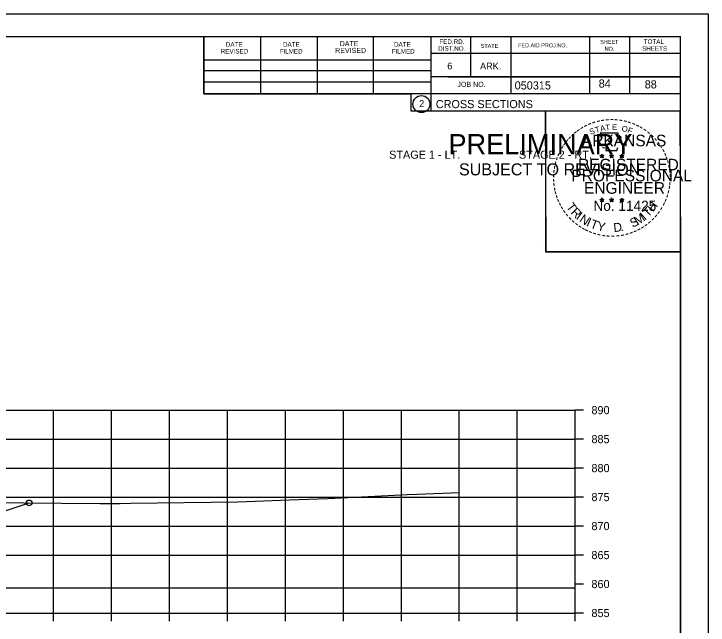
# Model space of a CAD drawing. Extents: x 1486524 to 1499135, y 326561 to 337924.
# Drawn here: x 1489026 to 1489145.8, y 335447.3 to 335552.7 of the extents above; entities that cross this region are included whole.
import ezdxf

# ---------------------------------------------------------------- set-up
doc = ezdxf.new("R2010")
doc.units = 0
for name, color, linetype in [('Default', 7, 'Continuous'), ('E_Const Align', 7, 'Continuous'), ('E_Const Align Station', 7, 'Continuous'), ('E_Ownership Information', 7, 'Continuous'), ('E_Property Line', 7, 'Continuous'), ('E_Quarter Calls', 7, 'Continuous'), ('E_Section Line', 7, 'Continuous'), ('E_Station Offset', 7, 'Continuous'), ('E_Title Sheet', 7, 'Continuous'), ('E_Tract Number', 7, 'Continuous'), ('S_SIXTEEN_SECTION', 7, 'Continuous')]:
    doc.layers.add(name, color=color, linetype=linetype)

msp = doc.modelspace()

# ---------------------------------------------------------------- linework, layer by layer
at = {"layer": 'E_Const Align'}
for p, q in [((1489122.89, 335449.34), (1489122.89, 335484.34)), ((1489124.29, 335484.34), (1489122.89, 335484.34)), ((1489124.29, 335479.34), (1489122.89, 335479.34)), ((1489124.29, 335474.34), (1489122.89, 335474.34)), ((1489124.29, 335469.34), (1489122.89, 335469.34)), ((1489124.29, 335464.34), (1489122.89, 335464.34)), ((1489124.29, 335459.34), (1489122.89, 335459.34)), ((1489124.29, 335454.34), (1489122.89, 335454.34)), ((1488842.89, 335449.34), (1489122.89, 335449.34)), ((1489032.89, 335447.94), (1489032.89, 335449.34)), ((1489042.89, 335447.94), (1489042.89, 335449.34)), ((1489052.89, 335447.94), (1489052.89, 335449.34)), ((1489062.89, 335447.94), (1489062.89, 335449.34)), ((1489072.89, 335447.94), (1489072.89, 335449.34)), ((1489082.89, 335447.94), (1489082.89, 335449.34)), ((1489092.89, 335447.94), (1489092.89, 335449.34)), ((1489102.89, 335447.94), (1489102.89, 335449.34)), ((1489112.89, 335447.94), (1489112.89, 335449.34)), ((1489122.89, 335447.94), (1489122.89, 335449.34)), ((1489124.29, 335449.34), (1489122.89, 335449.34))]:
    msp.add_line(p, q, dxfattribs=at)
at = {"layer": 'E_Ownership Information'}
for p, q in [((1488842.89, 335484.34), (1489122.89, 335484.34)), ((1489032.89, 335449.34), (1489032.89, 335484.34)), ((1489042.89, 335449.34), (1489042.89, 335484.34)), ((1489052.89, 335449.34), (1489052.89, 335484.34)), ((1489062.89, 335449.34), (1489062.89, 335484.34)), ((1489072.89, 335449.34), (1489072.89, 335484.34)), ((1489082.89, 335449.34), (1489082.89, 335484.34)), ((1489092.89, 335449.34), (1489092.89, 335484.34)), ((1489102.89, 335449.34), (1489102.89, 335484.34)), ((1489112.89, 335449.34), (1489112.89, 335484.34)), ((1489122.89, 335449.34), (1489122.89, 335484.34)), ((1488842.89, 335479.34), (1489122.89, 335479.34)), ((1488842.89, 335474.34), (1489122.89, 335474.34)), ((1488842.89, 335469.34), (1489122.89, 335469.34)), ((1488842.89, 335464.34), (1489122.89, 335464.34)), ((1488842.89, 335459.34), (1489122.89, 335459.34)), ((1488842.69, 335453.71), (1489122.69, 335453.71)), ((1488842.89, 335449.34), (1489122.89, 335449.34))]:
    msp.add_line(p, q, dxfattribs=at)
at = {"layer": 'E_Property Line'}
for p, q in [((1488824.89, 335548.8), (1489141.07, 335548.8)), ((1489058.81, 335538.92), (1489058.81, 335548.8)), ((1489097.97, 335548.8), (1489097.97, 335536)), ((1489104.81, 335548.8), (1489104.81, 335541.86)), ((1489111.75, 335548.8), (1489111.75, 335538.92)), ((1489125.33, 335548.8), (1489125.33, 335538.92)), ((1489132.27, 335548.8), (1489132.27, 335538.92)), ((1489141.07, 335343.34), (1489141.07, 335548.8)), ((1489068.67, 335538.92), (1489068.67, 335548.6)), ((1489078.43, 335538.92), (1489078.43, 335548.6)), ((1489088.11, 335538.92), (1489088.11, 335548.6)), ((1489141.07, 335545.86), (1489097.97, 335545.86)), ((1489141.07, 335545.88), (1489141.07, 335545.88)), ((1489058.81, 335544.78), (1489097.97, 335544.78)), ((1489058.81, 335542.92), (1489097.97, 335542.92)), ((1489141.07, 335541.86), (1489097.97, 335541.86)), ((1489100.93, 335541.86), (1489141.07, 335541.86)), ((1489058.81, 335538.92), (1489058.81, 335540.98)), ((1489058.81, 335540.98), (1489097.97, 335540.98)), ((1489141.07, 335538.92), (1489058.81, 335538.92)), ((1489097.97, 335536), (1489141.07, 335536))]:
    msp.add_line(p, q, dxfattribs=at)
msp.add_circle((1489096.35, 335537.14), 1.47, dxfattribs=at)
at = {"layer": 'E_Quarter Calls'}
for p, q in [((1488812.48, 335552.7), (1489145.82, 335552.7)), ((1489117.1, 335513.55), (1489117.1, 335513.55))]:
    msp.add_line(p, q, dxfattribs=at)
for points in [[(1488812.48, 335552.7), (1489145.82, 335552.7), (1489145.82, 335339.36), (1488812.48, 335339.36)], [(1489058.81, 335548.8), (1489058.81, 335538.92), (1489094.54, 335538.92), (1489094.54, 335536), (1489117.74, 335536), (1489117.74, 335511.67), (1489141.07, 335511.67), (1489141.07, 335343.34), (1488824.89, 335343.34), (1488824.89, 335548.8)], [(1489117.74, 335536), (1489140.94, 335536), (1489141.07, 335511.67), (1489117.86, 335511.67)]]:
    msp.add_lwpolyline(points, close=True, dxfattribs=at)
msp.add_circle((1489028.67, 335468.33), 0.5, dxfattribs=at)
at = {"layer": 'E_Title Sheet'}
msp.add_lwpolyline([(1488930.55, 335466.05), (1488940.89, 335462.61), (1488946.74, 335464.07), (1488952.89, 335465.61), (1488958.89, 335465.85), (1488982.89, 335466.47), (1488994.89, 335466.78), (1489002.89, 335466.99), (1489008.22, 335465.65), (1489012.89, 335464.49), (1489015.01, 335463.78), (1489028.67, 335468.33)], dxfattribs=at)
at = {"layer": 'E_Tract Number'}
msp.add_lwpolyline([(1489021.13, 335468.38), (1489040.88, 335468.26), (1489043.85, 335468.24), (1489044.38, 335468.24), (1489046.19, 335468.27), (1489064.69, 335468.53), (1489073.53, 335468.87), (1489080.23, 335469.08), (1489087.19, 335469.45), (1489093.9, 335469.76), (1489095.55, 335469.85), (1489102.91, 335470.14)], dxfattribs=at)
at = {"layer": 'S_SIXTEEN_SECTION'}
for p, q in [((1489127.5, 335528.51), (1489127.46, 335528.26)), ((1489127.5, 335528.15), (1489127.5, 335528.51)), ((1489127.5, 335528.51), (1489127.55, 335528.26)), ((1489129.17, 335528.51), (1489129.13, 335528.26)), ((1489129.17, 335528.15), (1489129.17, 335528.51)), ((1489129.17, 335528.51), (1489129.22, 335528.26)), ((1489130.93, 335528.5), (1489130.89, 335528.25)), ((1489130.93, 335528.14), (1489130.93, 335528.5)), ((1489130.93, 335528.5), (1489130.98, 335528.25)), ((1489127.15, 335528.26), (1489127.5, 335528.15)), ((1489127.15, 335528.26), (1489127.4, 335528.22)), ((1489127.15, 335528.26), (1489127.39, 335528.14)), ((1489127.28, 335527.85), (1489127.5, 335528.15)), ((1489127.28, 335527.85), (1489127.41, 335528.1)), ((1489127.28, 335527.85), (1489127.5, 335528.07)), ((1489127.85, 335528.26), (1489127.5, 335528.15)), ((1489127.71, 335527.85), (1489127.5, 335528.15)), ((1489127.71, 335527.85), (1489127.5, 335528.07)), ((1489127.85, 335528.26), (1489127.56, 335528.21)), ((1489127.71, 335527.85), (1489127.58, 335528.14)), ((1489127.85, 335528.26), (1489127.64, 335528.16)), ((1489128.82, 335528.26), (1489129.17, 335528.15)), ((1489128.82, 335528.26), (1489129.07, 335528.22)), ((1489128.82, 335528.26), (1489129.06, 335528.14)), ((1489128.95, 335527.85), (1489129.17, 335528.15)), ((1489128.95, 335527.85), (1489129.08, 335528.1)), ((1489128.95, 335527.85), (1489129.17, 335528.07)), ((1489129.52, 335528.26), (1489129.17, 335528.15)), ((1489129.38, 335527.85), (1489129.17, 335528.15)), ((1489129.38, 335527.85), (1489129.17, 335528.07)), ((1489129.52, 335528.26), (1489129.23, 335528.21)), ((1489129.38, 335527.85), (1489129.25, 335528.14)), ((1489129.52, 335528.26), (1489129.31, 335528.16)), ((1489130.58, 335528.25), (1489130.93, 335528.14)), ((1489130.58, 335528.25), (1489130.84, 335528.2)), ((1489130.58, 335528.25), (1489130.82, 335528.13)), ((1489130.72, 335527.84), (1489130.93, 335528.14)), ((1489130.72, 335527.84), (1489130.84, 335528.08)), ((1489130.72, 335527.84), (1489130.93, 335528.06)), ((1489131.28, 335528.25), (1489130.93, 335528.14)), ((1489131.15, 335527.84), (1489130.93, 335528.14)), ((1489131.15, 335527.84), (1489130.93, 335528.05)), ((1489131.28, 335528.25), (1489130.99, 335528.2)), ((1489131.15, 335527.84), (1489131.01, 335528.13)), ((1489131.28, 335528.25), (1489131.08, 335528.15)), ((1489127.15, 335520.69), (1489127.5, 335520.58)), ((1489127.15, 335520.69), (1489127.4, 335520.64)), ((1489127.15, 335520.69), (1489127.38, 335520.57)), ((1489127.28, 335520.28), (1489127.5, 335520.58)), ((1489127.28, 335520.28), (1489127.41, 335520.52)), ((1489127.28, 335520.28), (1489127.49, 335520.5)), ((1489127.5, 335520.94), (1489127.45, 335520.69)), ((1489127.71, 335520.28), (1489127.49, 335520.49)), ((1489127.5, 335520.58), (1489127.5, 335520.94)), ((1489127.5, 335520.94), (1489127.54, 335520.69)), ((1489127.84, 335520.69), (1489127.5, 335520.58)), ((1489127.71, 335520.28), (1489127.5, 335520.58)), ((1489127.84, 335520.69), (1489127.56, 335520.64)), ((1489127.71, 335520.28), (1489127.57, 335520.57)), ((1489127.84, 335520.69), (1489127.64, 335520.59)), ((1489128.82, 335520.69), (1489129.16, 335520.58)), ((1489128.82, 335520.69), (1489129.07, 335520.64)), ((1489128.82, 335520.69), (1489129.05, 335520.57)), ((1489128.95, 335520.28), (1489129.16, 335520.58)), ((1489128.95, 335520.28), (1489129.07, 335520.52)), ((1489128.95, 335520.28), (1489129.16, 335520.5)), ((1489129.16, 335520.94), (1489129.12, 335520.69)), ((1489129.16, 335520.58), (1489129.16, 335520.94)), ((1489129.16, 335520.94), (1489129.21, 335520.69)), ((1489129.51, 335520.69), (1489129.16, 335520.58)), ((1489129.38, 335520.28), (1489129.16, 335520.58)), ((1489129.38, 335520.28), (1489129.16, 335520.49)), ((1489129.51, 335520.69), (1489129.23, 335520.64)), ((1489129.38, 335520.28), (1489129.24, 335520.57)), ((1489129.51, 335520.69), (1489129.31, 335520.59)), ((1489130.58, 335520.68), (1489130.93, 335520.57)), ((1489130.58, 335520.68), (1489130.84, 335520.63)), ((1489130.58, 335520.68), (1489130.82, 335520.56)), ((1489130.72, 335520.27), (1489130.93, 335520.57)), ((1489130.72, 335520.27), (1489130.84, 335520.51)), ((1489130.72, 335520.27), (1489130.93, 335520.49)), ((1489130.93, 335520.93), (1489130.89, 335520.68)), ((1489130.93, 335520.57), (1489130.93, 335520.93)), ((1489130.93, 335520.93), (1489130.98, 335520.68)), ((1489131.28, 335520.68), (1489130.93, 335520.57)), ((1489131.14, 335520.27), (1489130.93, 335520.57)), ((1489131.14, 335520.27), (1489130.93, 335520.48)), ((1489131.28, 335520.68), (1489130.99, 335520.63)), ((1489131.14, 335520.27), (1489131.01, 335520.56)), ((1489131.28, 335520.68), (1489131.07, 335520.58))]:
    msp.add_line(p, q, dxfattribs=at)
for points in [[(1489127.19, 335532.14), (1489127.46, 335531.31)], [(1489130.7, 335531.22), (1489130.84, 335531.5), (1489130.16, 335531.48), (1489130.31, 335532.14), (1489127.19, 335532.14)], [(1489127.68, 335529.72), (1489127.68, 335529.63), (1489128.25, 335529.61), (1489128.19, 335529.14), (1489130.06, 335529.14), (1489130.26, 335529.67)], [(1489127.5, 335528.51), (1489127.71, 335527.85), (1489127.15, 335528.26), (1489127.85, 335528.26), (1489127.28, 335527.85), (1489127.5, 335528.51)], [(1489129.17, 335528.51), (1489129.38, 335527.85), (1489128.82, 335528.26), (1489129.52, 335528.26), (1489128.95, 335527.85), (1489129.17, 335528.51)], [(1489130.93, 335528.5), (1489131.15, 335527.84), (1489130.58, 335528.25), (1489131.28, 335528.25), (1489130.72, 335527.84), (1489130.93, 335528.5)], [(1489127.5, 335520.94), (1489127.71, 335520.28), (1489127.15, 335520.69), (1489127.84, 335520.69), (1489127.28, 335520.28), (1489127.5, 335520.94)], [(1489129.16, 335520.94), (1489129.38, 335520.28), (1489128.82, 335520.69), (1489129.51, 335520.69), (1489128.95, 335520.28), (1489129.16, 335520.94)], [(1489130.93, 335520.93), (1489131.14, 335520.27), (1489130.58, 335520.68), (1489131.28, 335520.68), (1489130.72, 335520.27), (1489130.93, 335520.93)]]:
    msp.add_lwpolyline(points, dxfattribs=at)
for centre, radius in [((1489127.5, 335528.15), 0.172), ((1489127.5, 335528.15), 0.145), ((1489127.5, 335528.15), 0.116), ((1489127.5, 335528.15), 0.0991), ((1489127.5, 335528.15), 0.0747), ((1489127.5, 335528.15), 0.0495), ((1489127.5, 335528.15), 0.0296), ((1489129.17, 335528.15), 0.172), ((1489129.17, 335528.15), 0.145), ((1489129.17, 335528.15), 0.116), ((1489129.17, 335528.15), 0.0991), ((1489129.17, 335528.15), 0.0747), ((1489129.17, 335528.15), 0.0495), ((1489129.17, 335528.15), 0.0296), ((1489130.93, 335528.14), 0.172), ((1489130.93, 335528.14), 0.145), ((1489130.93, 335528.14), 0.116), ((1489130.93, 335528.14), 0.0991), ((1489130.93, 335528.14), 0.0747), ((1489130.93, 335528.14), 0.0495), ((1489130.93, 335528.14), 0.0296), ((1489127.49, 335520.58), 0.172), ((1489127.49, 335520.58), 0.145), ((1489127.49, 335520.58), 0.116), ((1489127.49, 335520.58), 0.0991), ((1489127.49, 335520.58), 0.0747), ((1489127.49, 335520.58), 0.0495), ((1489127.49, 335520.58), 0.0296), ((1489129.16, 335520.58), 0.172), ((1489129.16, 335520.58), 0.145), ((1489129.16, 335520.58), 0.116), ((1489129.16, 335520.58), 0.0991), ((1489129.16, 335520.58), 0.0747), ((1489129.16, 335520.58), 0.0495), ((1489129.16, 335520.58), 0.0296), ((1489130.93, 335520.57), 0.172), ((1489130.93, 335520.57), 0.145), ((1489130.93, 335520.57), 0.116), ((1489130.93, 335520.57), 0.0991), ((1489130.93, 335520.57), 0.0747), ((1489130.93, 335520.57), 0.0495), ((1489130.93, 335520.57), 0.0296)]:
    msp.add_circle(centre, radius, dxfattribs=at)

# ---------------------------------------------------------------- texts
at = {"layer": 'Default'}
for s, p in [('STAGE 1 - LT.', (1489090.78, 335527.71)), ('STAGE 2 - RT.', (1489113.18, 335527.71))]:
    msp.add_text(s, height=1.4, dxfattribs=at).set_placement(p)
at = {"layer": 'E_Const Align Station'}
for s, p in [('890', (1489125.69, 335483.64)), ('885', (1489125.69, 335478.64)), ('880', (1489125.69, 335473.64)), ('875', (1489125.69, 335468.64)), ('870', (1489125.69, 335463.64)), ('865', (1489125.69, 335458.64)), ('860', (1489125.69, 335453.64)), ('855', (1489125.69, 335448.64))]:
    msp.add_text(s, height=1.4, dxfattribs=at).set_placement(p)
at = {"layer": 'E_Property Line'}
for s, height, p in [('DATE', 0.782, (1489062.61, 335547.04)), ('DATE', 0.782, (1489072.47, 335547.04)), ('DATE', 0.879, (1489082.25, 335547.14)), ('DATE', 0.782, (1489091.63, 335547.04)), ('FED.RD.', 0.782, (1489099.45, 335547.52)), ('STATE', 0.684, (1489106.57, 335546.84)), ('FED.AID PROJ.NO.', 0.684, (1489113.03, 335546.94)), ('SHEET', 0.684, (1489127.19, 335547.52)), ('TOTAL', 0.782, (1489134.71, 335547.52)), ('REVISED', 0.782, (1489061.73, 335545.86)), ('FILMED', 0.782, (1489071.89, 335545.86)), ('REVISED', 0.879, (1489081.47, 335545.96)), ('FILMED', 0.782, (1489091.23, 335545.86)), ('DIST.NO.', 0.782, (1489099.25, 335546.34)), ('NO.', 0.684, (1489127.97, 335546.34)), ('SHEETS', 0.782, (1489134.43, 335546.34)), ('6', 1.17, (1489100.81, 335543.12)), ('ARK.', 1.172, (1489106.47, 335543.12)), ('JOB NO.', 0.879, (1489102.57, 335540.1)), ('050315', 1.4, (1489112.44, 335539.66)), ('2', 1.17, (1489095.97, 335536.65)), ('CROSS SECTIONS', 1.4, (1489098.83, 335536.44))]:
    msp.add_text(s, height=height, rotation=360, dxfattribs=at).set_placement(p)
at = {"layer": 'E_Section Line'}
for s, height, p in [('PRELIMINARY', 3.5, (1489101.02, 335528.47)), ('DWB', 0.01, (1489101.76, 335530.32)), ('SUBJECT TO REVISION', 2.0751, (1489102.83, 335524.84))]:
    msp.add_text(s, height=height, rotation=360, dxfattribs=at).set_placement(p)
at = {"layer": 'E_Station Offset'}
for s, p in [('84', (1489126.94, 335539.99)), ('88', (1489134.88, 335539.84))]:
    msp.add_text(s, height=1.4, dxfattribs=at).set_placement(p)
at = {"layer": 'S_SIXTEEN_SECTION'}
for s, height, rotation, p in [('-', 1.6, 13.6301, (1489126.69, 335533.51)), ('-', 1.6, 10.2193, (1489127.37, 335533.67)), ('-', 1.6, 5.8968, (1489128.1, 335533.78)), ('-', 1.6, 0.1862, (1489128.87, 335533.85)), ('-', 1.6, 357.743, (1489129.59, 335533.84)), ('-', 1.6, 352.1617, (1489130.34, 335533.78)), ('-', 1.6, 347.2049, (1489131.05, 335533.67)), ('-', 1.6, 34.0636, (1489124.08, 335532.31)), ('-', 1.6, 28.7918, (1489124.67, 335532.68)), ('-', 1.6, 24.3072, (1489125.31, 335533)), ('-', 1.6, 19.1761, (1489125.94, 335533.27)), ('T', 1, 16.4036, (1489126.46, 335532.15)), ('A', 1, 11.2132, (1489127.29, 335532.4)), ('T', 1, 6.0228, (1489128.14, 335532.56)), ('E', 1, 0.8323, (1489129.24, 335532.67)), ('O', 1, 350.4515, (1489130.84, 335532.46)), ('F', 1, 340.0707, (1489131.8, 335532.24)), ('-', 1.6, 342.3362, (1489131.69, 335533.51)), ('-', 1.6, 337.8551, (1489132.42, 335533.29)), ('-', 1.6, 334.1211, (1489133.06, 335533.02)), ('-', 1.6, 329.6409, (1489133.63, 335532.74)), ('-', 1.6, 42.9622, (1489122.59, 335531.12)), ('-', 1.6, 38.9507, (1489123.02, 335531.54)), ('-', 1.6, 36.2317, (1489123.5, 335531.91)), ('S', 1, 21.594, (1489125.55, 335531.82)), ('-', 1.6, 325.8627, (1489134.28, 335532.37)), ('-', 1.6, 320.5297, (1489134.89, 335531.95)), ('-', 1.6, 50.6142, (1489121.74, 335530.16)), ('-', 1.6, 48.423, (1489122.14, 335530.64)), ('ARKANSAS', 2, 360, (1489124.04, 335529.85)), ('-', 1.6, 315.5786, (1489135.49, 335531.46)), ('-', 1.6, 309.8797, (1489136.06, 335530.91)), ('-', 1.6, 58.0706, (1489121, 335529.06)), ('-', 1.6, 54.2325, (1489121.32, 335529.59)), ('-', 1.6, 306.6522, (1489136.58, 335530.31)), ('-', 1.4, 303.6753, (1489137.07, 335529.74)), ('-', 1.6, 67.7743, (1489120.43, 335527.84)), ('-', 1.6, 62.8713, (1489120.69, 335528.45)), ('-', 1.6, 299.6684, (1489137.39, 335529.13)), ('-', 1.6, 294.6628, (1489137.71, 335528.52)), ('-', 1.6, 75.461, (1489120.01, 335526.49)), ('-', 1.6, 72.3945, (1489120.21, 335527.21)), ('REGISTERED', 2, 360, (1489123.37, 335525.7)), ('DWB', 0.01, 360, (1489127.49, 335528.14)), ('DWB', 0.01, 360, (1489129.16, 335528.14)), ('DWB', 0.01, 360, (1489130.92, 335528.13)), ('-', 1.6, 290.5728, (1489137.97, 335527.94)), ('-', 1.6, 285.1233, (1489138.2, 335527.36)), ('-', 1.6, 81.2013, (1489119.88, 335525.78)), ('-', 1.6, 280.5493, (1489138.4, 335526.62)), ('-', 1.6, 89.0622, (1489119.78, 335524.39)), ('-', 1.6, 85.1863, (1489119.8, 335525.09)), ('PROFESSIONAL', 2, 360, (1489122.22, 335523.8)), ('-', 1.6, 276.5962, (1489138.56, 335525.85)), ('-', 1.6, 274.3301, (1489138.62, 335525.13)), ('-', 1.6, 94.1959, (1489119.81, 335523.66)), ('ENGINEER', 2, 360, (1489124.41, 335521.67)), ('-', 1.6, 263.5172, (1489138.64, 335523.83)), ('-', 1.6, 269.9407, (1489138.66, 335524.5)), ('-', 1.6, 98.9479, (1489119.89, 335523)), ('-', 1.6, 101.7149, (1489120.02, 335522.26)), ('-', 1.6, 260.9953, (1489138.57, 335523.18)), ('-', 1.6, 105.4578, (1489120.18, 335521.67)), ('-', 1.6, 109.0874, (1489120.4, 335521.04)), ('-', 1.6, 252.8681, (1489138.28, 335521.78)), ('-', 1.6, 255.7626, (1489138.46, 335522.5)), ('-', 1.6, 114.0643, (1489120.65, 335520.44)), ('-', 1.6, 115.7289, (1489120.96, 335519.82)), ('T', 1.54, 306.0406, (1489121.25, 335519.41)), ('No. 11425', 1.757, 360, (1489126.03, 335518.72)), ('DWB', 0.01, 360, (1489127.48, 335520.57)), ('DWB', 0.01, 360, (1489129.15, 335520.57)), ('DWB', 0.01, 360, (1489130.92, 335520.56)), ('H', 1.54, 54.6088, (1489136.38, 335518.45)), ('-', 1.6, 244.6197, (1489137.79, 335520.48)), ('-', 1.6, 247.8887, (1489138.05, 335521.11)), ('-', 1.6, 120.4471, (1489121.31, 335519.24)), ('-', 1.6, 125.8934, (1489121.72, 335518.68)), ('R', 1.54, 314.005, (1489122.02, 335518.37)), ('T', 1.54, 46.6444, (1489135.49, 335517.51)), ('-', 1.6, 239.0712, (1489137.4, 335519.73)), ('-', 1.6, 130.7181, (1489122.18, 335518.12)), ('-', 1.6, 134.2238, (1489122.7, 335517.58)), ('I', 1.54, 321.9694, (1489122.92, 335517.43)), ('N', 1.54, 326.5002, (1489123.49, 335516.96)), ('S', 1.54, 26.9312, (1489132.8, 335515.78)), ('M', 1.54, 32.6563, (1489133.64, 335516.18)), ('I', 1.54, 42.1136, (1489134.92, 335517.03)), ('-', 1.6, 231.2538, (1489136.56, 335518.51)), ('-', 1.6, 233.8452, (1489136.99, 335519.08)), ('-', 1.6, 138.9338, (1489123.22, 335517.11)), ('-', 1.6, 144.6463, (1489123.78, 335516.71)), ('I', 1.54, 335.3603, (1489124.69, 335516.18)), ('T', 1.54, 339.8912, (1489125.35, 335515.85)), ('Y', 1.54, 347.8556, (1489126.57, 335515.4)), ('D', 1.54, 6.3969, (1489129.56, 335515.05)), ('-', 1.6, 215.7363, (1489135.01, 335516.96)), ('-', 1.6, 221.0851, (1489135.56, 335517.44)), ('-', 1.6, 225.7653, (1489136.09, 335517.95)), ('-', 1.6, 148.0898, (1489124.34, 335516.34)), ('-', 1.6, 151.5704, (1489124.92, 335516.01)), ('-', 1.6, 154.6002, (1489125.44, 335515.77)), ('-', 1.6, 158.5612, (1489126.06, 335515.51)), ('.', 1.54, 13.7642, (1489130.75, 335515.17)), ('-', 1.6, 204.2516, (1489133.3, 335515.91)), ('-', 1.6, 207.3568, (1489133.92, 335516.23)), ('-', 1.6, 212.2491, (1489134.48, 335516.58)), ('-', 1.6, 162.7983, (1489126.75, 335515.3)), ('-', 1.6, 167.5555, (1489127.46, 335515.13)), ('-', 1.6, 173.1155, (1489128.24, 335515.02)), ('-', 1.6, 176.5183, (1489128.98, 335514.97)), ('-', 1.6, 181.5918, (1489129.73, 335514.99)), ('-', 1.6, 185.8167, (1489130.54, 335515.07)), ('-', 1.6, 191.2858, (1489131.27, 335515.2)), ('-', 1.6, 195.4743, (1489132, 335515.4)), ('-', 1.6, 200.7184, (1489132.68, 335515.64))]:
    msp.add_text(s, height=height, rotation=rotation, dxfattribs=at).set_placement(p)

doc.saveas('drawing.dxf')
